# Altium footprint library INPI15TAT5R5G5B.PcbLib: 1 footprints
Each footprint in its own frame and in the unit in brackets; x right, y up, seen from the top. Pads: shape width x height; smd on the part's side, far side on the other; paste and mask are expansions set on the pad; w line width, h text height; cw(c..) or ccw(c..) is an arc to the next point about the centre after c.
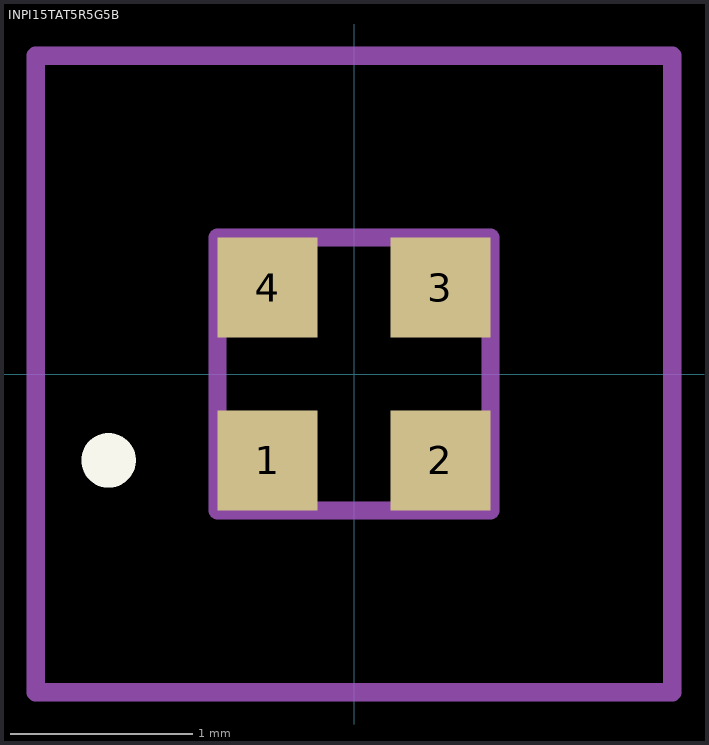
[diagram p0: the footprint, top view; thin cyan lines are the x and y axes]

## INPI15TAT5R5G5B [mm]
pads (4):
  rect 0.55x0.55 smd: 1(-0.475,-0.475) 2(0.475,-0.475) 3(0.475,0.475) 4(-0.475,0.475)
Top Overlay:
  lines w0.2: -1.4,-0.475 -1.4,-0.475 ; -1.4,-0.475 ccw(c-1.35,-0.475) -1.3,-0.475 ; -1.4,-0.475 cw(c-1.35,-0.475) -1.3,-0.475 ; -1.4,-0.475 -1.4,-0.475 ; -1.4,-0.475 ccw(c-1.35,-0.475) -1.3,-0.475 ; -1.3,-0.475 -1.3,-0.475
Mechanical 15:
  lines w0.1: -0.75,-0.75 0.75,-0.75 0.75,0.75 -0.75,0.75 -0.75,-0.75
Mechanical 20:
  lines w0.1: -1.75,-1.75 1.75,-1.75 1.75,1.75 -1.75,1.75 -1.75,-1.75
